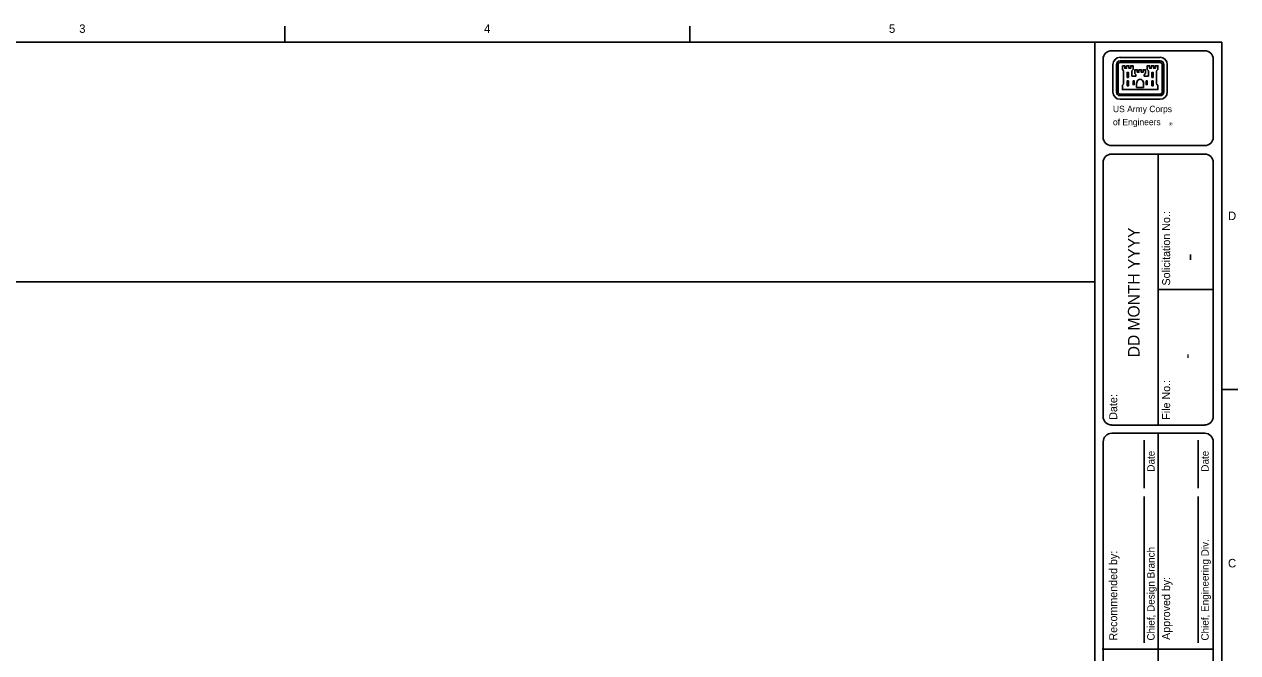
# Model space of a CAD drawing. Extents: x -1.36 to 2.79, y 0.03 to 1.79.
# Drawn here: x 1.298 to 2.791, y 1.02 to 1.793 of the extents above; entities that cross this region are included whole.
import ezdxf

# ---------------------------------------------------------------- set-up
doc = ezdxf.new("R2010")
doc.units = 0
for name, color, linetype in [('G-ANNO-LEGN', 7, 'Continuous'), ('G-ANNO-SYMB', 7, 'Continuous'), ('G-ANNO-TEXT', 7, 'Continuous'), ('G-ANNO-TTLB', 7, 'Continuous')]:
    doc.layers.add(name, color=color, linetype=linetype)

msp = doc.modelspace()

# ---------------------------------------------------------------- linework, layer by layer
at = {"layer": 'G-ANNO-LEGN'}
msp.add_line((2.6146, 1.4763), (0.125, 1.4763), dxfattribs=at)
msp.add_line((2.6146, 1.4763), (0.125, 1.4763), dxfattribs=at)
at = {"layer": 'G-ANNO-SYMB'}
for p, q in [((2.6952, 1.7523), (2.6458, 1.7523)), ((2.6458, 1.7523), (2.6458, 1.7523)), ((2.6458, 1.7479), (2.6952, 1.7479)), ((2.6371, 1.7434), (2.6371, 1.7097)), ((2.6414, 1.7097), (2.6414, 1.7434)), ((2.6414, 1.7434), (2.6414, 1.7434)), ((2.6433, 1.7434), (2.6433, 1.7097)), ((2.6952, 1.7459), (2.6458, 1.7459)), ((2.6952, 1.7459), (2.6952, 1.7459)), ((2.6976, 1.7097), (2.6976, 1.7434)), ((2.6996, 1.7434), (2.6996, 1.7097)), ((2.7039, 1.7097), (2.7039, 1.7434)), ((2.6661, 1.715), (2.6661, 1.72)), ((2.6748, 1.72), (2.6748, 1.715)), ((2.6458, 1.7072), (2.6952, 1.7072)), ((2.6952, 1.7052), (2.6458, 1.7052)), ((2.6748, 1.715), (2.6661, 1.715)), ((2.6458, 1.7008), (2.6952, 1.7008))]:
    msp.add_line(p, q, dxfattribs=at)
for points in [[(2.6487, 1.7419), (2.6487, 1.7374), (2.6501, 1.7359), (2.6501, 1.7195), (2.6487, 1.718), (2.6487, 1.7127), (2.6923, 1.7127), (2.6923, 1.718), (2.6908, 1.7195), (2.6908, 1.7359), (2.6923, 1.7374), (2.6923, 1.7419), (2.6894, 1.7419), (2.6894, 1.7389), (2.6872, 1.7389), (2.6872, 1.7419), (2.6843, 1.7419), (2.6843, 1.7389), (2.6821, 1.7389), (2.6821, 1.7419), (2.6792, 1.7419), (2.6792, 1.7374), (2.6807, 1.7359), (2.6807, 1.7292), (2.6756, 1.7292), (2.6756, 1.731), (2.677, 1.7325), (2.677, 1.737), (2.6741, 1.737), (2.6741, 1.734), (2.6719, 1.734), (2.6719, 1.737), (2.669, 1.737), (2.669, 1.734), (2.6669, 1.734), (2.6669, 1.737), (2.664, 1.737), (2.664, 1.7325), (2.6654, 1.731), (2.6654, 1.7292), (2.6603, 1.7292), (2.6603, 1.7359), (2.6618, 1.7374), (2.6618, 1.7419), (2.6589, 1.7419), (2.6589, 1.7389), (2.6567, 1.7389), (2.6567, 1.7419), (2.6538, 1.7419), (2.6538, 1.7389), (2.6516, 1.7389), (2.6516, 1.7419), (2.6487, 1.7419)], [(2.6545, 1.7277), (2.656, 1.7277), (2.656, 1.7337), (2.6545, 1.7337), (2.6545, 1.7277)], [(2.685, 1.7336), (2.6851, 1.7337)], [(2.685, 1.7277), (2.6865, 1.7277), (2.6865, 1.7337), (2.685, 1.7337), (2.685, 1.7277)], [(2.6545, 1.7172), (2.656, 1.7172), (2.656, 1.7232), (2.6545, 1.7232), (2.6545, 1.7172)], [(2.6618, 1.7232), (2.6632, 1.7232), (2.6632, 1.7187), (2.6618, 1.7187), (2.6618, 1.7232)], [(2.6778, 1.7232), (2.6792, 1.7232), (2.6792, 1.7187), (2.6778, 1.7187), (2.6778, 1.7232)], [(2.685, 1.7172), (2.6865, 1.7172), (2.6865, 1.7232), (2.685, 1.7232), (2.685, 1.7172)], [(2.6864, 1.7277), (2.6865, 1.7277)]]:
    msp.add_lwpolyline(points, dxfattribs=at)
for centre, major_axis, ratio, start_param, end_param in [((2.6458, 1.7434), (0, -0.00897), 0.971851, 3.141593, 4.712389), ((2.6458, 1.7434), (0, -0.00449), 0.971851, 3.141593, 4.712389), ((2.6952, 1.7434), (0, 0.00897), 0.971851, 4.712389, 6.283185), ((2.6952, 1.7434), (0, 0.00449), 0.971851, 4.712389, 6.283185), ((2.6458, 1.7434), (0, -0.00252), 0.971851, 3.141593, 4.712389), ((2.6952, 1.7434), (0, 0.00252), 0.971851, 4.712389, 6.283185), ((2.6705, 1.72), (0, 0.00542), 0.804513, 4.712389, 7.853982), ((2.6458, 1.7097), (0, -0.00897), 0.971851, 4.712389, 6.283185), ((2.6458, 1.7097), (0, -0.00449), 0.971851, 4.712389, 6.283185), ((2.6458, 1.7097), (0, -0.00252), 0.971851, 4.712389, 6.283185), ((2.6952, 1.7097), (0, -0.00897), 0.971851, 0, 1.570796), ((2.6952, 1.7097), (0, -0.00449), 0.971851, 0, 1.570796), ((2.6952, 1.7097), (0, -0.00252), 0.971851, 0, 1.570796)]:
    msp.add_ellipse(centre, major_axis=major_axis, ratio=ratio, start_param=start_param, end_param=end_param, dxfattribs=at)
at = {"layer": 'G-ANNO-TTLB'}
for p, q in [((1.6188, 1.7905), (1.6188, 1.7708)), ((2.1167, 1.7905), (2.1167, 1.7708)), ((2.6927, 1.6333), (2.6927, 1.3001)), ((2.6927, 1.4667), (2.7604, 1.4667)), ((2.7708, 1.3438), (2.7905, 1.3438)), ((2.6927, 1.2899), (2.6927, 1.0245)), ((2.6753, 1.2814), (2.6753, 1.2224)), ((2.7418, 1.2814), (2.7418, 1.2224)), ((2.6753, 1.212), (2.6753, 1.0322)), ((2.7418, 1.212), (2.7418, 1.0322)), ((2.7593, 1.0245), (2.6239, 1.0245)), ((2.6928, 1.0245), (2.6928, 0.7591))]:
    msp.add_line(p, q, dxfattribs=at)
for points in [[(0.125, 1.7708), (2.6146, 1.7708), (2.6146, 0.0625), (0.125, 0.0625)], [(2.6146, 0.0625), (2.7708, 0.0625), (2.7708, 1.7708), (2.6146, 1.7708)]]:
    msp.add_lwpolyline(points, close=True, dxfattribs=at)
for points in [[(2.625, 1.6542), (2.625, 1.75)], [(2.6354, 1.7604), (2.75, 1.7604)], [(2.7604, 1.75), (2.7604, 1.6542)], [(2.75, 1.6438), (2.6354, 1.6438)], [(2.75, 1.6333), (2.6354, 1.6333)], [(2.625, 1.6229), (2.625, 1.3106)], [(2.7604, 1.3106), (2.7604, 1.6229)], [(2.6354, 1.3001), (2.75, 1.3001)], [(2.75, 1.2899), (2.6355, 1.2899)], [(2.625, 1.2795), (2.625, 0.5042)], [(2.7605, 0.5042), (2.7605, 1.2795)]]:
    msp.add_lwpolyline(points, dxfattribs=at)
for centre, start, end in [((2.6354, 1.75), 90, 180), ((2.75, 1.75), 360, 90), ((2.6354, 1.6542), 180, 270), ((2.75, 1.6542), 270, 0), ((2.6354, 1.6229), 90, 180.0015), ((2.75, 1.6229), 0.0015, 90), ((2.6354, 1.3106), 180.0015, 270), ((2.75, 1.3106), 270, 0.0015), ((2.6355, 1.2795), 90, 180), ((2.75, 1.2795), 360, 90)]:
    msp.add_arc(centre, 0.0104, start, end, dxfattribs=at)

# ---------------------------------------------------------------- texts
at = {"layer": 'G-ANNO-SYMB'}
for s, height, p in [('US Army Corps', 0.007812, (2.6371, 1.6849)), ('of Engineers', 0.007812, (2.6371, 1.6688)), ('®', 0.00417, (2.7059, 1.6682))]:
    msp.add_text(s, height=height, dxfattribs=at).set_placement(p)
at = {"layer": 'G-ANNO-TEXT'}
for s, p in [('3', (1.3658, 1.7824)), ('4', (1.8637, 1.7824)), ('5', (2.3616, 1.7824)), ('D', (2.7786, 1.5521)), ('C', (2.7786, 1.125))]:
    msp.add_text(s, height=0.0104, dxfattribs=at).set_placement(p)
for s, height, p in [('Solicitation No.:', 0.009843, (2.7074, 1.4717)), ('DD MONTH YYYY', 0.014323, (2.6698, 1.3834)), ('-', 0.0208, (2.7405, 1.5019)), ('-', 0.0143, (2.7349, 1.3817)), ('File No.:', 0.00984, (2.7074, 1.3066)), ('Date:', 0.00984, (2.6423, 1.3066)), ('Date', 0.00911, (2.6883, 1.2427)), ('Date', 0.00911, (2.7548, 1.2427)), ('Chief, Design Branch', 0.009115, (2.6883, 1.035)), ('Chief, Engineering Div.', 0.009115, (2.7548, 1.035)), ('Recommended by:', 0.009843, (2.6423, 1.035)), ('Approved by:', 0.009843, (2.7074, 1.0358))]:
    msp.add_text(s, height=height, rotation=90, dxfattribs=at).set_placement(p)

doc.saveas('drawing.dxf')
